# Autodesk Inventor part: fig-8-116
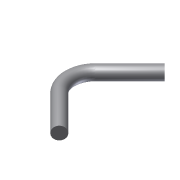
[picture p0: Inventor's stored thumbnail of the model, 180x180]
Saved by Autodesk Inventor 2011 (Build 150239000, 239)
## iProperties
Created: 2007-02
Part Number: fig-8-116
Document SubType Name: Modeling
Designer: Administrator
Density: 1 g/cm^3
Author: Administrator
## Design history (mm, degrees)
node "Sketch1"
sketch "Sketch2"
  geometry: C1 r 5 at (0, 0); 1 further point
  constraints: 1 centre point, 1 coincident, 1 other
  dimensions: "d0" = 10 diameter of C1
extrude "Extrusion1" new body sketch "Sketch2" stored distance "d1" = 100; taper "d2" = 0 deg
workplane "Work Plane1"
sketch "Sketch3"
  geometry: L1 (0, 11)-(0, -8)
  constraints: 2 end point, 1 vertical
feature "Bend Part2" sketch "Sketch3" dims "d5" = 15, "d6" = 90 deg
body "Solid1"
